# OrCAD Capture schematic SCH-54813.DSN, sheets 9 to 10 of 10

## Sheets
9 05 SPI/I2C/ATX/CT: size C
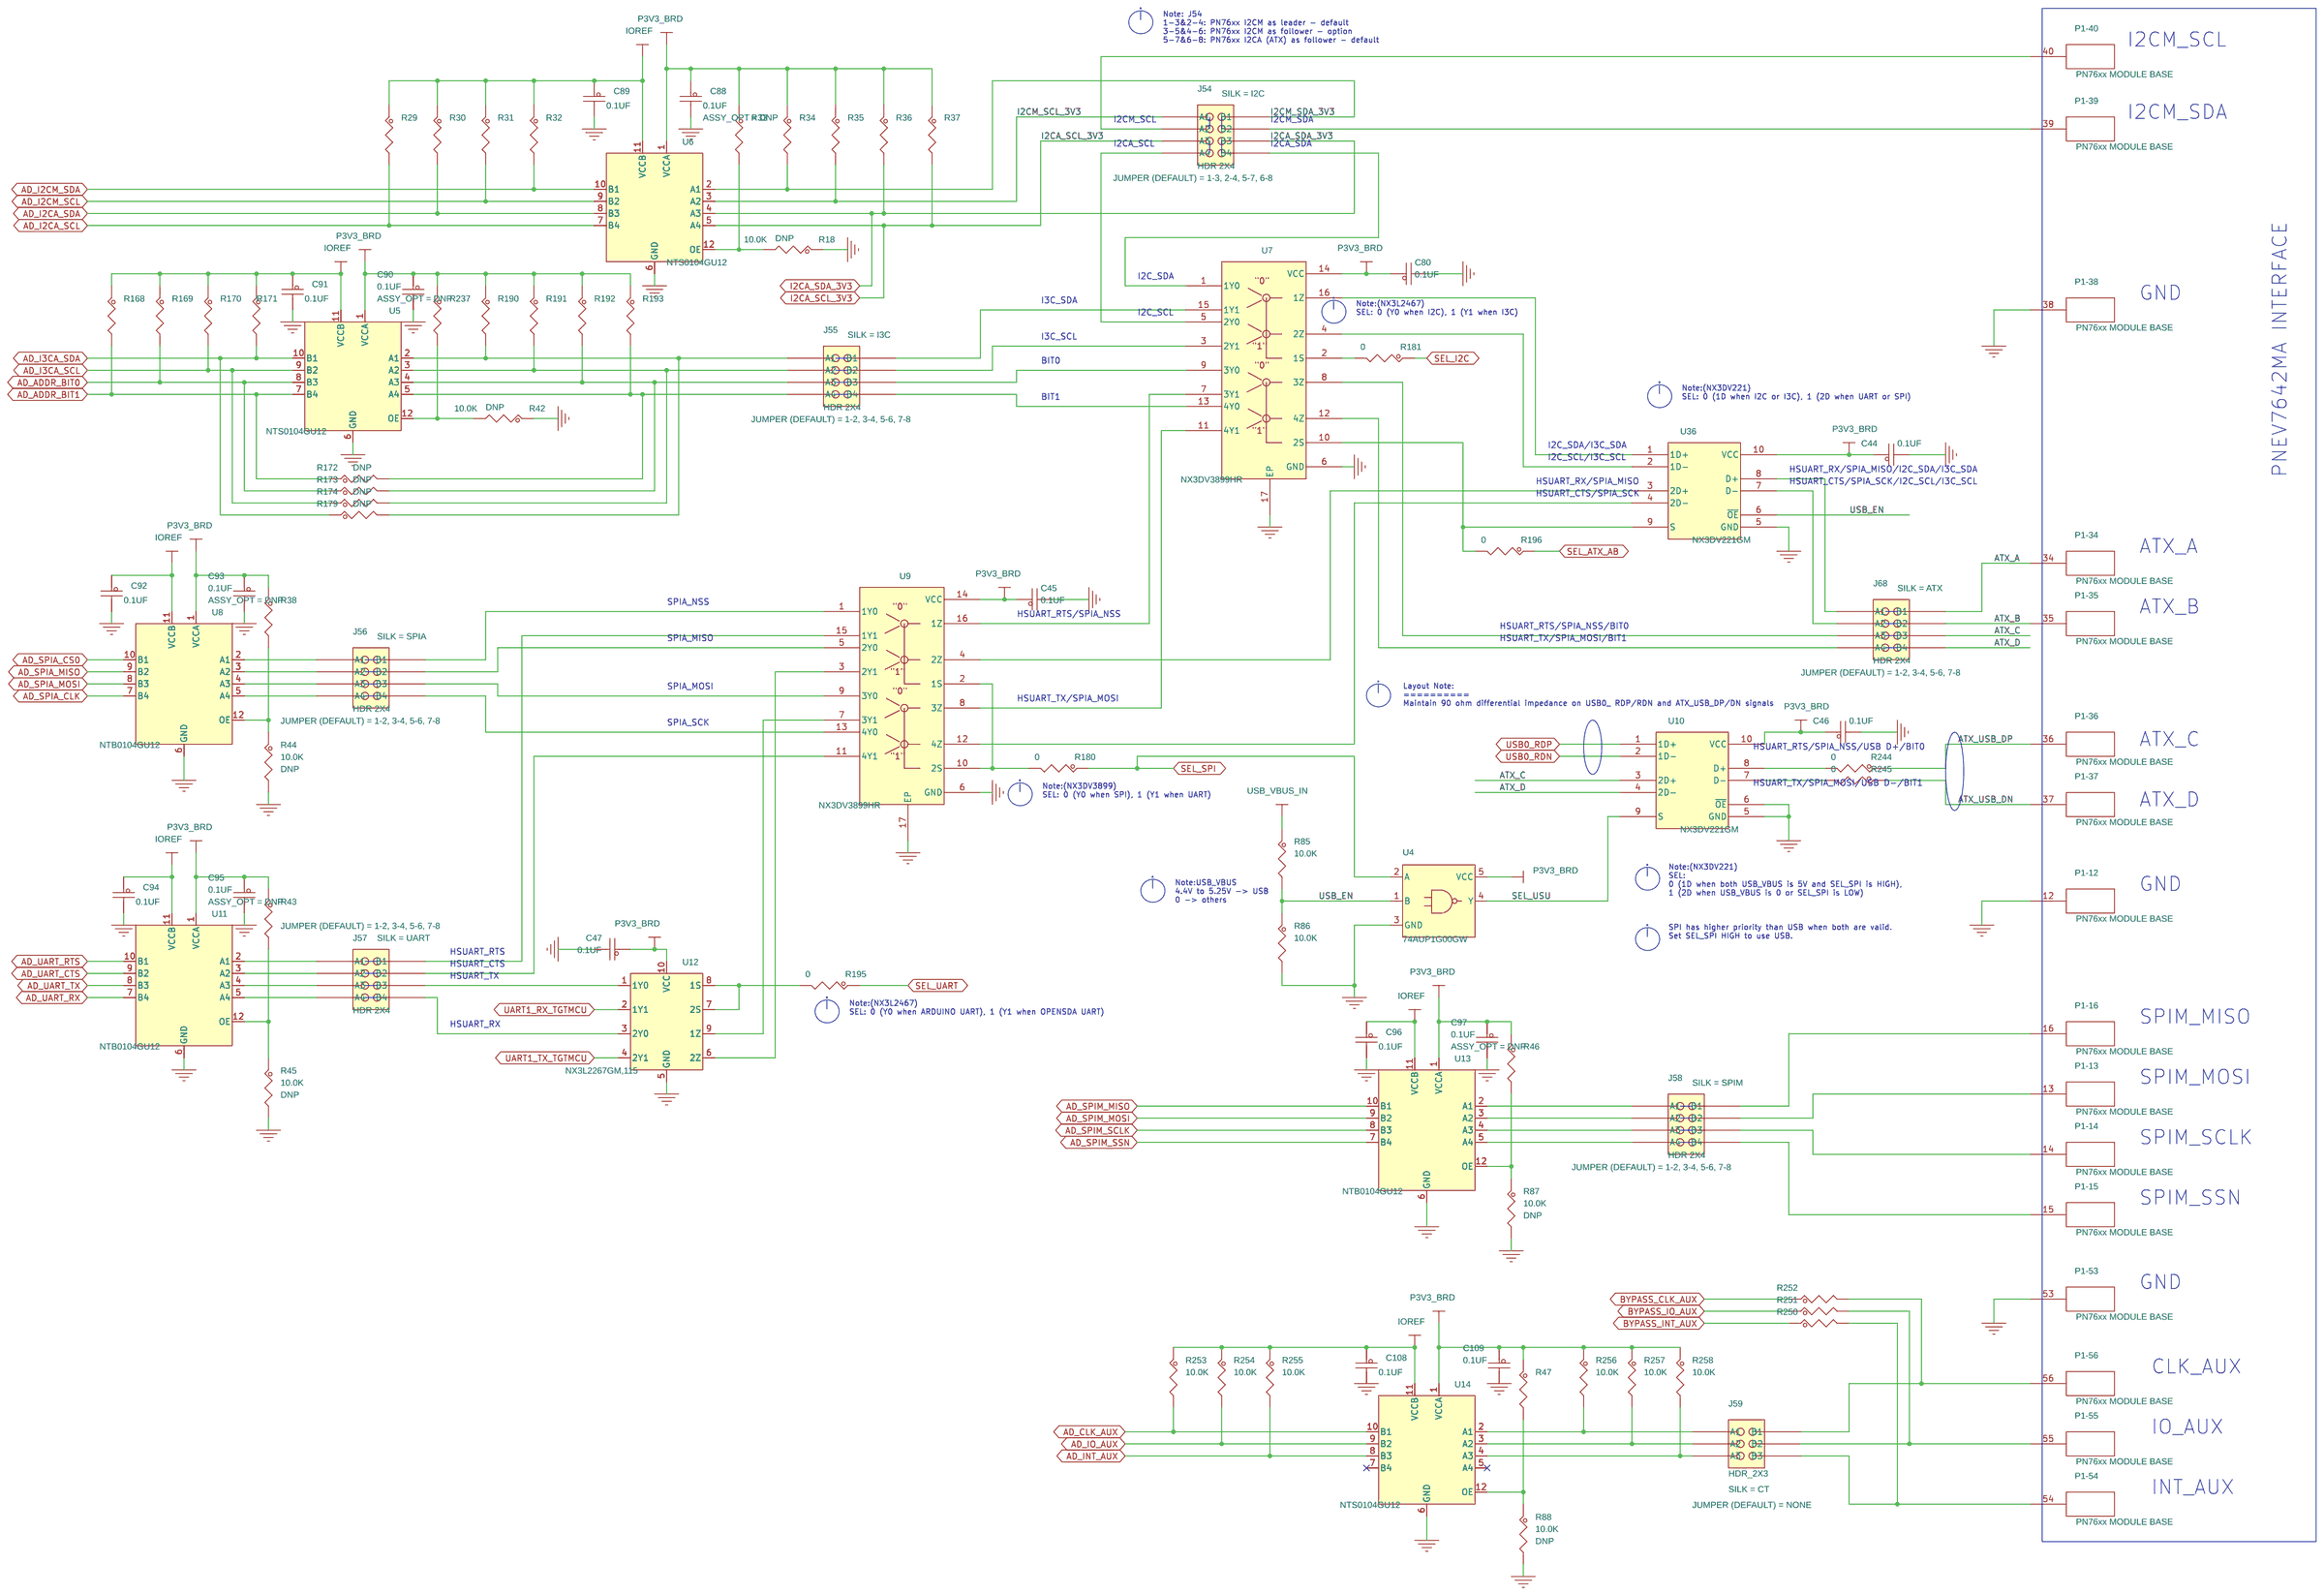
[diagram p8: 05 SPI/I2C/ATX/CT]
10 07 ANALOG/CONTROL: size C
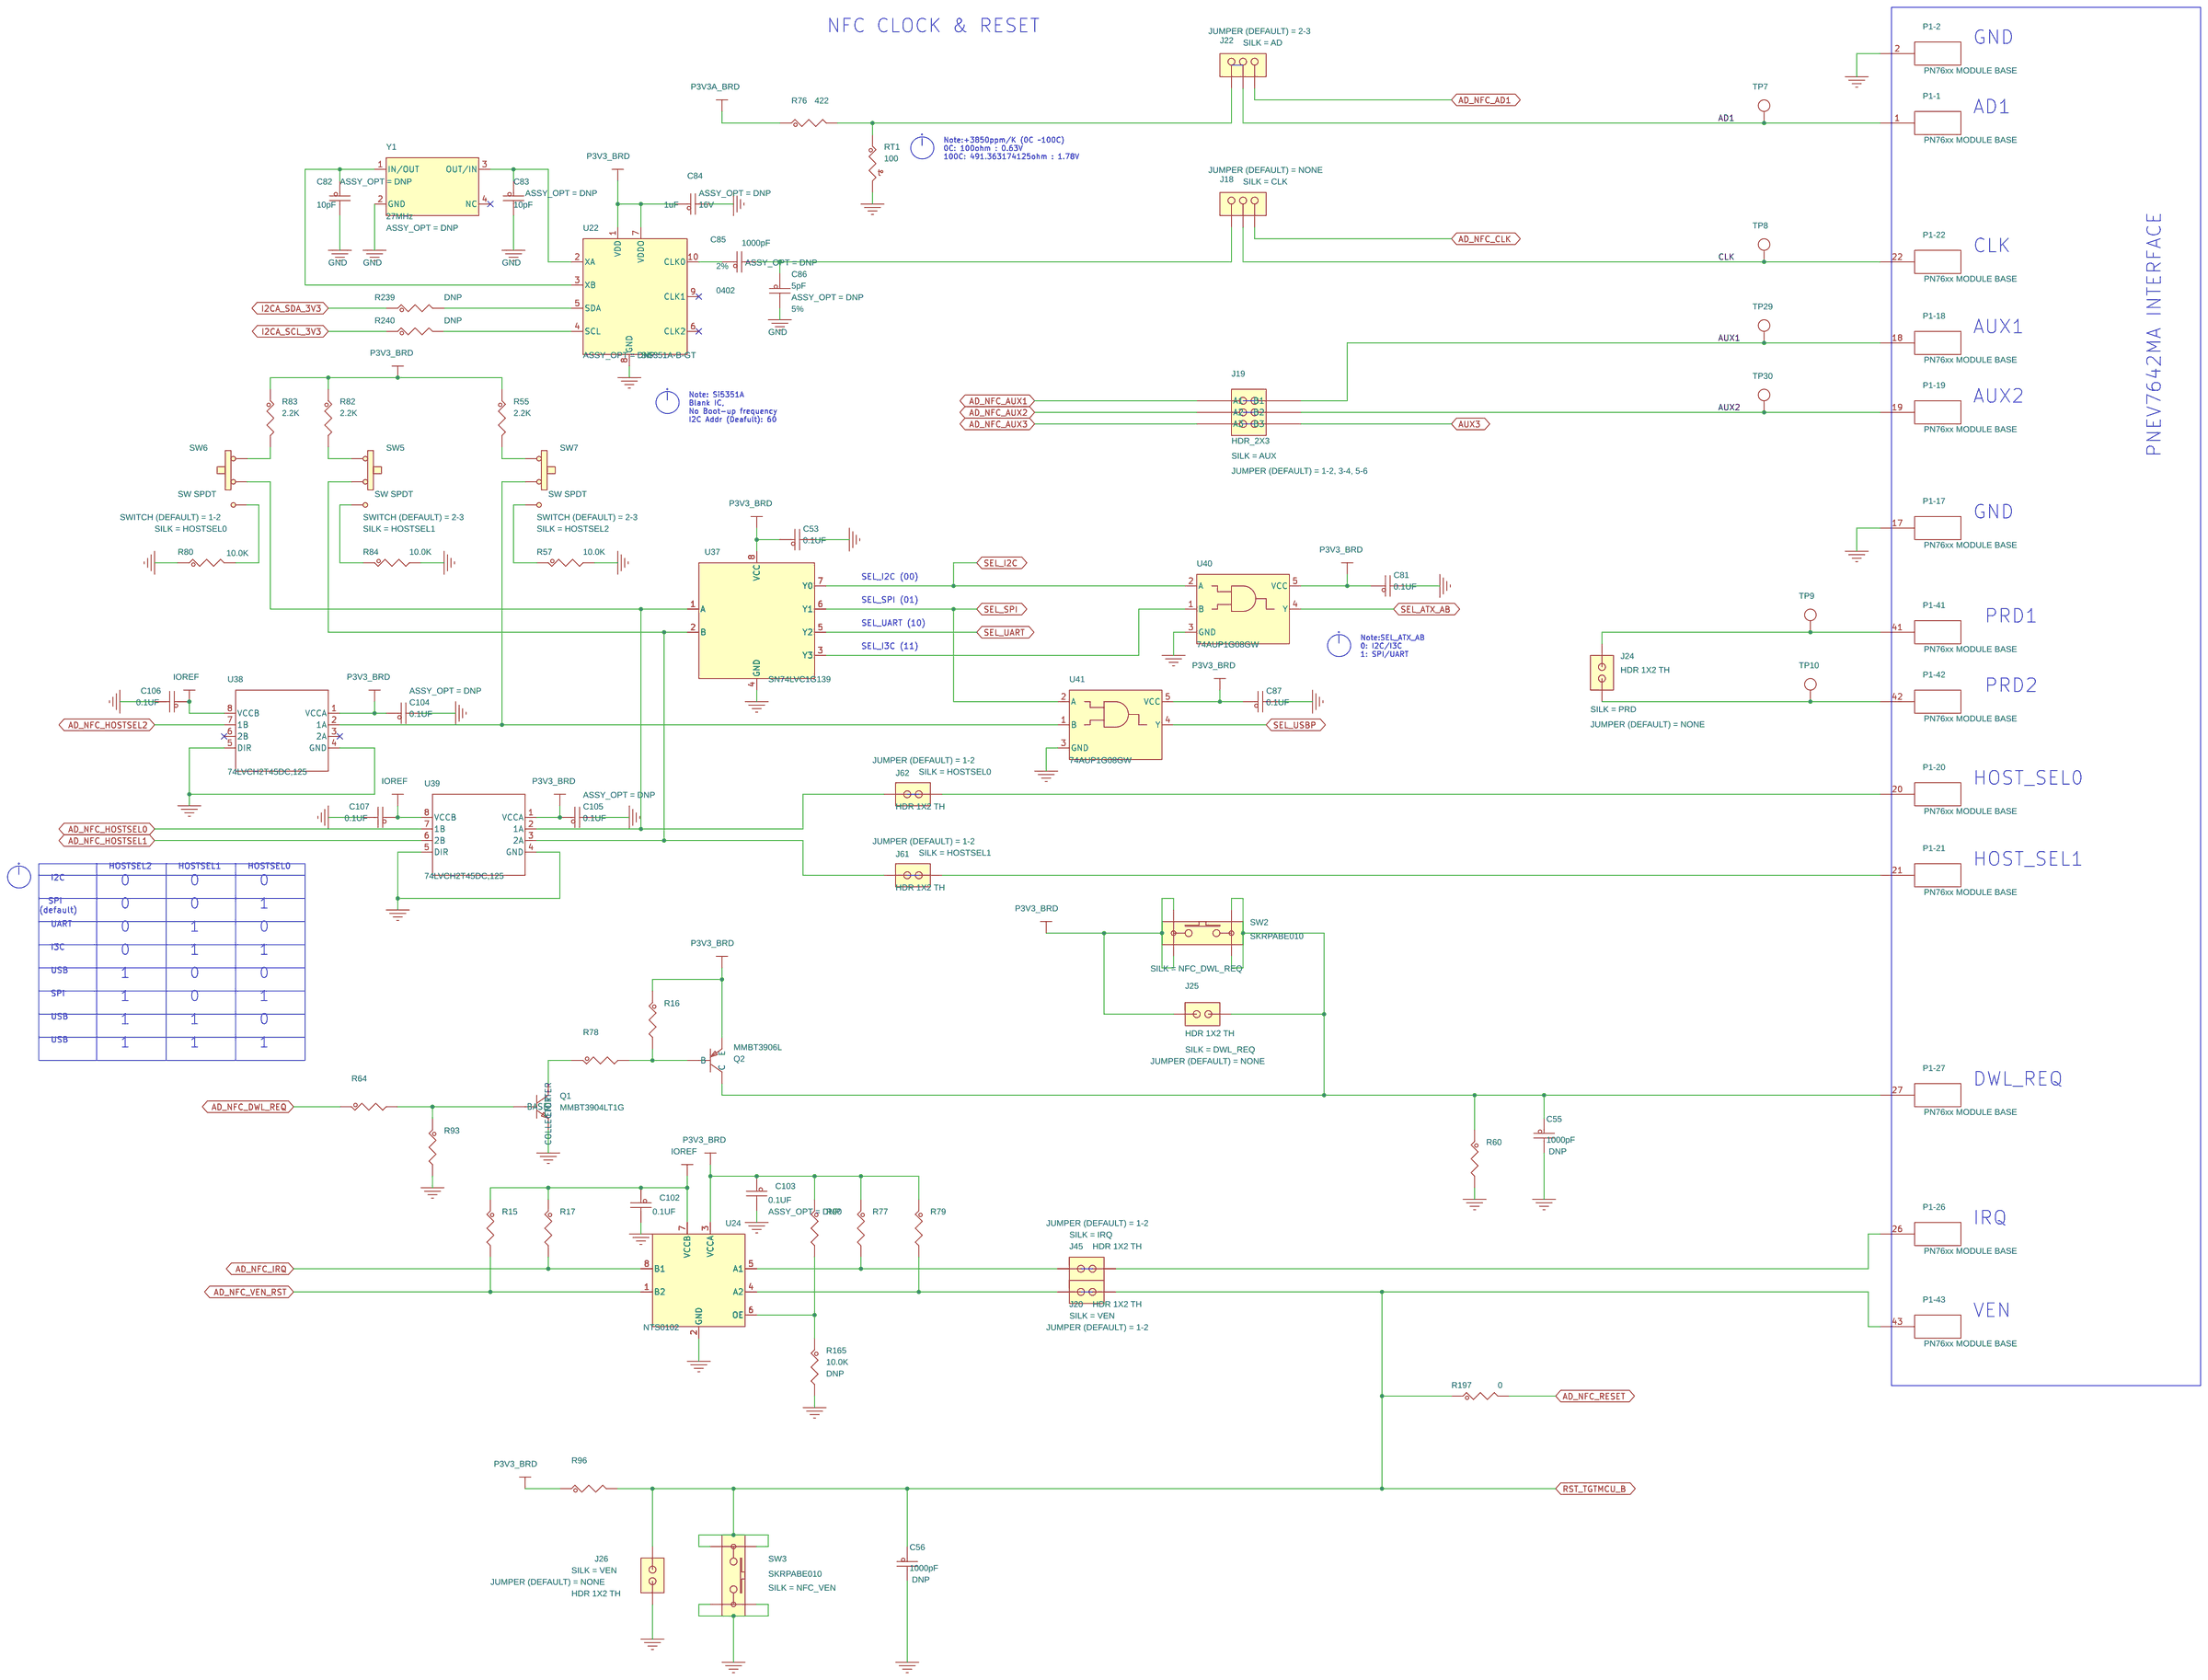
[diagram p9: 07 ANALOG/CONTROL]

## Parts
sheet 05 SPI/I2C/ATX/CT
C44  0.1UF  [CC0402_25]
C45  0.1UF  [CC0402_25]
C46  0.1UF  [CC0402_25]
C47  0.1UF  [CC0402_25]
C80  0.1UF  [CC0402_25]
C88  0.1UF  [CC0402_25]
C89  0.1UF  [CC0402_25]
C90  0.1UF  [CC0402_25]
C91  0.1UF  [CC0402_25]
C92  0.1UF  [CC0402_25]
C93  0.1UF  [CC0402_25]
C94  0.1UF  [CC0402_25]
C95  0.1UF  [CC0402_25]
C96  0.1UF  [CC0402_25]
C97  0.1UF  [CC0402_25]
C108  0.1UF  [CC0402_25]
C109  0.1UF  [CC0402_25]
J54  HDR 2X4  [HDR2X4]
J55  HDR 2X4  [HDR2X4]
J56  HDR 2X4  [HDR2X4]
J57  HDR 2X4  [HDR2X4]
J58  HDR 2X4  [HDR2X4]
J59  HDR_2X3  [HDR203]
J68  HDR 2X4  [HDR2X4]
R18  10.0K  [RC0402_25]
R29  4.7K  [RC0402_25]
R30  4.7K  [RC0402_25]
R31  4.7K  [RC0402_25]
R32  4.7K  [RC0402_25]
R33  4.7K  [RC0402_25]
R34  4.7K  [RC0402_25]
R35  4.7K  [RC0402_25]
R36  4.7K  [RC0402_25]
R37  4.7K  [RC0402_25]
R38  4.7K  [RC0402_25]
R42  10.0K  [RC0402_25]
R43  4.7K  [RC0402_25]
R44  10.0K  [RC0402_25]
R45  10.0K  [RC0402_25]
R46  4.7K  [RC0402_25]
R47  4.7K  [RC0402_25]
R85  10.0K  [RC0402_25]
R86  10.0K  [RC0402_25]
R87  10.0K  [RC0402_25]
R88  10.0K  [RC0402_25]
R168  4.7K  [RC0402_25]
R169  4.7K  [RC0402_25]
R170  4.7K  [RC0402_25]
R171  4.7K  [RC0402_25]
R172  0  [RC0603_OV]
R173  0  [RC0603_OV]
R174  0  [RC0603_OV]
R179  0  [RC0603_OV]
R180  0  [RC0603_OV]
R181  0  [RC0603_OV]
R190  4.7K  [RC0402_25]
R191  4.7K  [RC0402_25]
R192  4.7K  [RC0402_25]
R193  4.7K  [RC0402_25]
R195  0  [RC0603_OV]
R196  0  [RC0603_OV]
R237  4.7K  [RC0402_25]
R244  0  [RC0603_OV]
R245  0  [RC0603_OV]
R250  0  [RC0603_OV]
R251  0  [RC0603_OV]
R252  0  [RC0603_OV]
R253  10.0K  [RC0402_25]
R254  10.0K  [RC0402_25]
R255  10.0K  [RC0402_25]
R256  10.0K  [RC0402_25]
R257  10.0K  [RC0402_25]
R258  10.0K  [RC0402_25]
U4  74AUP1G00GW  [sc70-5]
U5  NTS0104GU12  [xqfn12_0p4_1p8x2p1]
U6  NTS0104GU12  [xqfn12_0p4_1p8x2p1]
U7  NX3DV3899HR  [QFN16_0P5_3X3_EP]
U8  NTB0104GU12  [xqfn12_0p4_1p8x2p1]
U9  NX3DV3899HR  [QFN16_0P5_3X3_EP]
U10  NX3DV221GM  [xqfn10_0p5_1p65x2p1]
U11  NTB0104GU12  [xqfn12_0p4_1p8x2p1]
U12  NX3L2267GM,115  [XQFN10_0P5_1P65X2P1]
U13  NTB0104GU12  [xqfn12_0p4_1p8x2p1]
U14  NTS0104GU12  [xqfn12_0p4_1p8x2p1]
U36  NX3DV221GM  [xqfn10_0p5_1p65x2p1]
sheet 06 GPIO/DEBUG
P1  PN76xx MODULE BASE  [module56_1p52_23x23mm]  (sections -1,-10,-11,-12,-13,-14,-15,-16,-17,-18,-19,-2,-20,-21,-22,-23,-24,-25,-26,-27,-28,-29,-3,-30,-31,-32,-33,-34,-35,-36,-37,-38,-39,-4,-40,-41,-42,-43,-44,-45,-46,-47,-48,-49,-5,-50,-51,-52,-53,-54,-55,-56,-57,-6,-7,-8,-9)
sheet 07 ANALOG/CONTROL
C53  0.1UF  [CC0402_25]
C55  1000pF  [CC0402_25]
C56  1000pF  [CC0402_25]
C81  0.1UF  [CC0402_25]
C82  10pF  [CC0402_25]
C83  10pF  [CC0402_25]
C84  1uF  [CC0603_OV]
C85  1000pF  [CC0402_25]
C86  5pF  [CC0402_25]
C87  0.1UF  [CC0402_25]
C102  0.1UF  [CC0402_25]
C103  0.1UF  [CC0402_25]
C104  0.1UF  [CC0402_25]
C105  0.1UF  [CC0402_25]
C106  0.1UF  [CC0402_25]
C107  0.1UF  [CC0402_25]
J18  HDR TH 1X3  [HDR103]
J19  HDR_2X3  [HDR203]
J20  HDR 1X2 TH  [HDR_1X2]
J22  HDR TH 1X3  [HDR103]
J24  HDR 1X2 TH  [HDR_1X2]
J25  HDR 1X2 TH  [HDR_1X2]
J26  HDR 1X2 TH  [HDR_1X2]
J45  HDR 1X2 TH  [HDR_1X2]
J61  HDR 1X2 TH  [HDR_1X2]
J62  HDR 1X2 TH  [HDR_1X2]
Q1  MMBT3904LT1G  [SOT23_A]
Q2  MMBT3906L  [SOT23]
R15  4.7K  [RC0402_25]
R16  10.0K  [RC0402_25]
R17  4.7K  [RC0402_25]
R55  2.2K  [RC0402_25]
R57  10.0K  [RC0402_25]
R60  10.0K  [RC0402_25]
R64  10.0K  [RC0402_25]
R76  422  [RC0603_OV]
R77  4.7K  [RC0402_25]
R78  10.0K  [RC0402_25]
R79  4.7K  [RC0402_25]
R80  10.0K  [RC0402_25]
R82  2.2K  [RC0402_25]
R83  2.2K  [RC0402_25]
R84  10.0K  [RC0402_25]
R90  4.7K  [RC0402_25]
R93  10.0K  [RC0402_25]
R96  10.0K  [RC0402_25]
R165  10.0K  [RC0402_25]
R197  0  [RC0603_OV]
R239  0  [RC0603_OV]
R240  0  [RC0603_OV]
RT1  100  [RC0603_OV]
SW2  SKRPABE010  [sw4_skrp]
SW3  SKRPABE010  [sw4_skrp]
SW5  SW SPDT  [SW3_SPDT_SLIDE]
SW6  SW SPDT  [SW3_SPDT_SLIDE]
SW7  SW SPDT  [SW3_SPDT_SLIDE]
TP7  TPAD_040  [TPAD_040]
TP8  TPAD_040  [TPAD_040]
TP9  TPAD_040  [TPAD_040]
TP10  TPAD_040  [TPAD_040]
TP29  TPAD_040  [TPAD_040]
TP30  TPAD_040  [TPAD_040]
U22  Si5351A-B-GT  [MSOP_10_0P5_3X3]
U24  NTS0102  [tssop8_a]
U37  SN74LVC1G139  [psop8]
U38  74LVCH2T45DC,125  [ssop8_dcu]
U39  74LVCH2T45DC,125  [ssop8_dcu]
U40  74AUP1G08GW  [sc70-5]
U41  74AUP1G08GW  [sc70-5]
Y1  27MHz  [xtal4_1p6x1p2]

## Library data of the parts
C44-C47 C53 C80 C81 C87 C89 C91 C92 C94 C96 C102 C106-C109 = CAP_NP: CAP CER 0.1UF 50V 10% X5R 0402; AGILE_PN: 150-79249; CAD_APPROVED: Yes; FPLIST: CC0402_25,CC0402_HD,0402_CC,capc0402_l; HEIGHT: 0.55MM; MFG_NAME01: MURATA; MFG_PN01: GRM155R61H104KE19; ROHS: Yes; Rated Voltage: 50V; TOL: 10%; Temp Range: -55C to +85C; Tolerance: 10%; VOLTAGE: 50V
C88 C90 C93 C95 C97 C103-C105 = CAP_NP: CAP CER 0.1UF 50V 10% X5R 0402; AGILE_PN: 150-79249; ASSY_OPT: DNP; CAD_APPROVED: Yes; FPLIST: CC0402_25,CC0402_HD,0402_CC,capc0402_l; HEIGHT: 0.55MM; MFG_NAME01: MURATA; MFG_PN01: GRM155R61H104KE19; ROHS: Yes; Rated Voltage: 50V; TOL: 10%; Temp Range: -55C to +85C; Tolerance: 10%; VOLTAGE: 50V
J54 = CONN_HDR_4X2: HDR 2X4 TH 100MIL CTR 338H AU 100L; 3D_Mechanical_Footprint_File: http://fcl.am.freescale.net/ALLEGRO/step/hdr2x4_100l.STEP; AGILE_PN: 210-81059; CAD_APPROVED: Yes; HEIGHT: 8.59MM; JUMPER (DEFAULT): 1-3, 2-4, 5-7, 6-8; MFG_NAME01: SAMTEC; MFG_PN01: TSW-104-07-F-D; ROHS: Yes; SILK: I2C; Temp Range: -55°C to +125°C
J55 = CONN_HDR_4X2: HDR 2X4 TH 100MIL CTR 338H AU 100L; 3D_Mechanical_Footprint_File: http://fcl.am.freescale.net/ALLEGRO/step/hdr2x4_100l.STEP; AGILE_PN: 210-81059; CAD_APPROVED: Yes; HEIGHT: 8.59MM; JUMPER (DEFAULT): 1-2, 3-4, 5-6, 7-8; MFG_NAME01: SAMTEC; MFG_PN01: TSW-104-07-F-D; ROHS: Yes; SILK: I3C; Temp Range: -55°C to +125°C
J56 = CONN_HDR_4X2: HDR 2X4 TH 100MIL CTR 338H AU 100L; 3D_Mechanical_Footprint_File: http://fcl.am.freescale.net/ALLEGRO/step/hdr2x4_100l.STEP; AGILE_PN: 210-81059; CAD_APPROVED: Yes; HEIGHT: 8.59MM; JUMPER (DEFAULT): 1-2, 3-4, 5-6, 7-8; MFG_NAME01: SAMTEC; MFG_PN01: TSW-104-07-F-D; ROHS: Yes; SILK: SPIA; Temp Range: -55°C to +125°C
J57 = CONN_HDR_4X2: HDR 2X4 TH 100MIL CTR 338H AU 100L; 3D_Mechanical_Footprint_File: http://fcl.am.freescale.net/ALLEGRO/step/hdr2x4_100l.STEP; AGILE_PN: 210-81059; CAD_APPROVED: Yes; HEIGHT: 8.59MM; JUMPER (DEFAULT): 1-2, 3-4, 5-6, 7-8; MFG_NAME01: SAMTEC; MFG_PN01: TSW-104-07-F-D; ROHS: Yes; SILK: UART; Temp Range: -55°C to +125°C
J58 = CONN_HDR_4X2: HDR 2X4 TH 100MIL CTR 338H AU 100L; 3D_Mechanical_Footprint_File: http://fcl.am.freescale.net/ALLEGRO/step/hdr2x4_100l.STEP; AGILE_PN: 210-81059; CAD_APPROVED: Yes; HEIGHT: 8.59MM; JUMPER (DEFAULT): 1-2, 3-4, 5-6, 7-8; MFG_NAME01: SAMTEC; MFG_PN01: TSW-104-07-F-D; ROHS: Yes; SILK: SPIM; Temp Range: -55°C to +125°C
J59 = CONN_HDR_3X2: HDR 2X3 TH 100MIL CTR 338H AU 100L; 3D_Mechanical_Footprint_File: http://fcl.am.freescale.net/ALLEGRO/step/hdr203.STEP; AGILE_PN: 210-81057; CAD_APPROVED: Yes; HEIGHT: 8.59MM; JUMPER (DEFAULT): NONE; MFG_NAME01: SAMTEC; MFG_PN01: TSW-103-07-F-D; ROHS: Yes; SILK: CT; Temp Range: -55°C to +125°C
J68 = CONN_HDR_4X2: HDR 2X4 TH 100MIL CTR 338H AU 100L; 3D_Mechanical_Footprint_File: http://fcl.am.freescale.net/ALLEGRO/step/hdr2x4_100l.STEP; AGILE_PN: 210-81059; CAD_APPROVED: Yes; HEIGHT: 8.59MM; JUMPER (DEFAULT): 1-2, 3-4, 5-6, 7-8; MFG_NAME01: SAMTEC; MFG_PN01: TSW-104-07-F-D; ROHS: Yes; SILK: ATX; Temp Range: -55°C to +125°C
R18 R42 R44 R45 R87 R88 R165 = RES: RES MF 10.0K 1/16W 1% AEC-Q200 0402; AGILE_PN: 470-75416; ASSY_OPT: DNP; CAD_APPROVED: Yes; FPLIST: RC0402_25,RC0402_HD,0402_CC; HEIGHT: 0.4MM; MFG_NAME01: KOA SPEER; MFG_PN01: RK73H1ETTP1002F; ROHS: Yes; SIGNAL_MODEL: DEFAULT_RESISTOR_10000OHM_2_1; TOL: 5%; Temp Range: –55 °C to +155 °C; Tolerance: 1%
R15 R17 R29-R38 R43 R46 R47 R77 R79 R90 R168-R171 R190-R193 R237 = RES: RES MF 4.70K 1/16W 1% 0402; AGILE_PN: 470-75418; CAD_APPROVED: Yes; FPLIST: RC0402_25,RC0402_HD,0402_CC; HEIGHT: 0.4mm; MFG_NAME01: WALSIN TECHNOLOGY CORP.; MFG_PN01: WR04X4701FTL; ROHS: Yes; TOL: 1%; Tolerance: 1%; VOLTAGE: 1/16W
R57 R80 R84-R86 R253-R258 = RES: RES MF 10.0K 1/16W 1% AEC-Q200 0402; AGILE_PN: 470-75416; CAD_APPROVED: Yes; FPLIST: RC0402_25,RC0402_HD,0402_CC; HEIGHT: 0.4MM; MFG_NAME01: KOA SPEER; MFG_PN01: RK73H1ETTP1002F; ROHS: Yes; SIGNAL_MODEL: DEFAULT_RESISTOR_10000OHM_2_1; TOL: 5%; Temp Range: –55 °C to +155 °C; Tolerance: 1%
R172-R174 R179 R239 R240 = RES: RES MF ZERO OHM 1/10W -- 0603; AGILE_PN: 470-80866; ASSY_OPT: DNP; CAD_APPROVED: Yes; FPLIST: RC0603_OV,RC0603,R603-X2,0603_CC,IND_0603HP_NSP,CC0603_OV_NSP; HEIGHT: 0.6MM; MFG_NAME01: YAGEO AMERICA; MFG_PN01: RC0603FR-070RL; ROHS: Yes; TOL: 5%; Temp Range: –55 °C to +155 °C
R180 R181 R195-R197 R244 R245 = RES: RES MF ZERO OHM 1/10W -- 0603; AGILE_PN: 470-80866; CAD_APPROVED: Yes; FPLIST: RC0603_OV,RC0603,R603-X2,0603_CC; HEIGHT: 0.6MM; MFG_NAME01: YAGEO AMERICA; MFG_PN01: RC0603FR-070RL; ROHS: Yes; TOL: 1%; Temp Range: –55 °C to +155 °C
R250-R252 = RES: RES MF ZERO OHM 1/10W -- 0603; AGILE_PN: 470-80866; CAD_APPROVED: Yes; FPLIST: RC0603_OV,RC0603,R603-X2,0603_CC,IND_0603HP_NSP,CC0603_OV_NSP; HEIGHT: 0.6MM; MFG_NAME01: YAGEO AMERICA; MFG_PN01: RC0603FR-070RL; ROHS: Yes; TOL: 5%; Temp Range: –55 °C to +155 °C
U4 = 74AUP1G00GW: IC GATE NAND 2IN 0.8-3.6V.TSSOP5; 3D_Mechanical_Footprint_File: http://fcl.am.freescale.net/ALLEGRO/step/sc70-5.STEP; AGILE_PN: 312-81222; CAD_APPROVED: Yes; HEIGHT: 1.1MM; MFG_NAME01: NEXPERIA; MFG_PN01: 74AUP1G00GW,125; ROHS: Yes; VOLTAGE: 0.8-3.6V.
U5 U6 U14 = NTS0104GU12_12P: IC DUAL VXLTR XCVR 4BIT 1.65-3.6/2.3-5.5V XQFN12; 3D_Mechanical_Footprint_File: http://fcl.am.freescale.net/ALLEGRO/step/xqfn12_0p4_1p8x2p1.step; AGILE_PN: 312-82046; CAD_APPROVED: Yes; HEIGHT: 0.5MM; MFG_NAME01: NXP SEMICONDUCTORS; ROHS: Yes; Temp Range: -40 to +125C; VOLTAGE: 1.65-3.6/2.3-5.5V
U7 U9 = NX3DV3899HR: IC LIN SW DPDT 1.4-4.3V QFN16; 3D_Mechanical_Footprint_File: http://fcl.am.freescale.net/ALLEGRO/step/qfn16_0p5_3x3_ep.STEP; AGILE_PN: 315-80655; CAD_APPROVED: Yes; HEIGHT: 0.5MM; MFG_NAME01: NXP SEMICONDUCTORS; MFG_PN01: NX3DV3899HRZ; ROHS: Yes; VOLTAGE: 1.4-4.3V
U8 U11 U13 = NTB0104GU12_12P: IC DUAL VXLTR XCVR 4BIT 1.2-3.6/1.65-5.5V XQFN12; 3D_Mechanical_Footprint_File: http://fcl.am.freescale.net/ALLEGRO/step/xqfn12_0p4_1p8x2p1.step; AGILE_PN: 312-81869; CAD_APPROVED: Yes; HEIGHT: 0.5MM; MFG_NAME01: NXP SEMICONDUCTORS; ROHS: Yes; Temp Range: -40C to +125C; VOLTAGE: 1.2-3.6/1.65-5.5V
U10 U36 = NX3DV221GM_QFN_10P: IC USB 2.0 SWITCH HS 2.3-3.6V XQFN10; 3D_Mechanical_Footprint_File: http://fcl.am.freescale.net/ALLEGRO/step/xqfn10_0p5_1p65x2p1.step; AGILE_PN: 315-80882; CAD_APPROVED: Yes; HEIGHT: 0.5MM; MFG_NAME01: NXP SEMICONDUCTORS; MFG_PN01: NX3DV221GM,115; ROHS: Yes; VOLTAGE: 2.3-3.6V
U12 = NX3L2267GM_QFN10: IC ANALOG SW DUAL SPDT 1.4-4.3V XQFN10; 3D_Mechanical_Footprint_File: http://fcl.am.freescale.net/ALLEGRO/step/xqfn10_0p5_1p65x2p1.step; AGILE_PN: 315-81532; CAD_APPROVED: Yes; HEIGHT: 0.5 MM; MFG_NAME01: NXP SEMICONDUCTORS; ROHS: Yes; Temp Range: -40°C to +125°C; VOLTAGE: 1.4-4.3V
P1 = TP_RECT_56P_EP: NFC MODULE 4X14 23X23MM NO PART TO ORDER; AGILE_PN: 510-78458; CAD_APPROVED: Yes; HEIGHT: 2.35 MM; ROHS: Yes
C55 C56 = CAP_NP: CAP CER 1000pF 50V 10% X7R AEC-Q200 0402; AGILE_PN: 150-79040; ASSY_OPT: DNP; CAD_APPROVED: Yes; FPLIST: CC0402_25,CC0402_HD,0402_CC; HEIGHT: 0.55MM; MFG_NAME01: MURATA; MFG_PN01: GCM155R71H102KA37D; Package Size: 0402; Package Type: Paper Tape; ROHS: Yes; Rated Voltage: 50V; Temp Range: -55C to +125C; Tolerance: 10%; VOLTAGE: 50V
C82 C83 = CAP_NP: CAP CER 10pF 50V 2% C0G 0402; AGILE_PN: 150-78893; ASSY_OPT: DNP; CAD_APPROVED: Yes; FPLIST: CC0402_25,CC0402_HD,0402_CC; HEIGHT: 0.55 MM; MFG_NAME01: MURATA; MFG_PN01: GJM1555C1H100GB01D; Package Size: 0402; Package Type: 180mm Paper Tape; ROHS: Yes; Rated Voltage: 50V; SIZE: 0402; Temp Range: -55C to +125C; Temp_Range: -55°C to +125°C; Tolerance: 2%; VOLTAGE: 50V
C84 = CAP_NP: CAP CER 1uF 16V 10% X7R 0603; AGILE_PN: 150-79460; ASSY_OPT: DNP; CAD_APPROVED: Yes; FPLIST: CC0603_OV,CC0603,0603_CC; HEIGHT: 0.9 MM; MFG_NAME01: TDK; MFG_PN01: C1608X7R1C105K080AC; Package Size: 0603; ROHS: Yes; Rated Voltage: 16V; Temp Range: -55C to +125C; Tolerance: 10%; VOLTAGE: 16V
C85 = CAP_NP: CAP CER 1000pF 50V 2% C0G 0402; AGILE_PN: 150-79726; ASSY_OPT: DNP; CAD_APPROVED: Yes; FPLIST: CC0402_25,CC0402_HD,0402_CC; HEIGHT: 0.55MM; MFG_NAME01: MURATA; MFG_PN01: GRM1555C1H102GA01D; Package Size: 0402; Package Type: SMD; ROHS: Yes; Rated Voltage: 50V; SIZE: 0402; Temp Range: -55C to +125C; Temp_Range: -55°C to +125°C; Tolerance: 2%; VOLTAGE: 50V
C86 = CAP_NP: CAP CER 5PF 16V 5% C0G CC0402; AGILE_PN: 150-75578; ASSY_OPT: DNP; CAD_APPROVED: Yes; FPLIST: CC0402_25,CC0402_HD,0402_CC; HEIGHT: 0.55 MM; MFG_NAME01: SMEC; MFG_PN01: MCCA050J0NOTF; ROHS: Yes; Rated Voltage: 16V; Temp Range: -55C to +125C; Temp_Range: -55°C to +125°C; Tolerance: 5%; VOLTAGE: 16V
J18 = CONN_HDR_3X1: HDR 1X3 TH 100MIL SP 339H AU 100L; 3D_Mechanical_Footprint_File: http://fcl.am.freescale.net/ALLEGRO/step/hdr103.STEP; AGILE_PN: 210-75726; CAD_APPROVED: Yes; HEIGHT: 8.65MM; JUMPER (DEFAULT): NONE; MFG_NAME01: SAMTEC; MFG_PN01: TSW-103-07-G-S; Package Size: 7.62 x 2.54 mm; ROHS: Yes; SILK: CLK; Temp Range: -55°C to +125°C; VOLTAGE: 450 - 550 VAC
J19 = CONN_HDR_3X2: HDR 2X3 TH 100MIL CTR 338H AU 100L; 3D_Mechanical_Footprint_File: http://fcl.am.freescale.net/ALLEGRO/step/hdr203.STEP; AGILE_PN: 210-81057; CAD_APPROVED: Yes; HEIGHT: 8.59MM; JUMPER (DEFAULT): 1-2, 3-4, 5-6; MFG_NAME01: SAMTEC; MFG_PN01: TSW-103-07-F-D; ROHS: Yes; SILK: AUX; Temp Range: -55°C to +125°C
J20 = HDR_1X2_TH: HDR 1X2 TH 100MIL SP 339H AU 98L; 3D_Mechanical_Footprint_File: http://fcl.am.freescale.net/ALLEGRO/step/hdr102_338h.STEP; AGILE_PN: 210-75439; CAD_APPROVED: YES; FPLIST: HDR102,SH_HDR102_BOTTOM; HEIGHT: 8.71 MM; JUMPER (DEFAULT): 1-2; MFG_NAME01: SAMTEC; MFG_PN01: TSW-102-07-G-S; ROHS: Yes; SILK: VEN; Temp Range: -55°C to +125°C
J22 = CONN_HDR_3X1: HDR 1X3 TH 100MIL SP 339H AU 100L; 3D_Mechanical_Footprint_File: http://fcl.am.freescale.net/ALLEGRO/step/hdr103.STEP; AGILE_PN: 210-75726; CAD_APPROVED: Yes; HEIGHT: 8.65MM; JUMPER (DEFAULT): 2-3; MFG_NAME01: SAMTEC; MFG_PN01: TSW-103-07-G-S; Package Size: 7.62 x 2.54 mm; ROHS: Yes; SILK: AD; Temp Range: -55°C to +125°C; VOLTAGE: 450 - 550 VAC
J24 = HDR_1X2_TH: HDR 1X2 TH 100MIL SP 339H AU 98L; 3D_Mechanical_Footprint_File: http://fcl.am.freescale.net/ALLEGRO/step/hdr102_338h.STEP; AGILE_PN: 210-75439; CAD_APPROVED: YES; FPLIST: HDR102,SH_HDR102_BOTTOM; HEIGHT: 8.71 MM; JUMPER (DEFAULT): NONE; MFG_NAME01: SAMTEC; MFG_PN01: TSW-102-07-G-S; ROHS: Yes; SILK: PRD; Temp Range: -55°C to +125°C
J25 = HDR_1X2_TH: HDR 1X2 TH 100MIL SP 339H AU 98L; 3D_Mechanical_Footprint_File: http://fcl.am.freescale.net/ALLEGRO/step/hdr102_338h.STEP; AGILE_PN: 210-75439; CAD_APPROVED: YES; FPLIST: HDR102,SH_HDR102_BOTTOM; HEIGHT: 8.71 MM; JUMPER (DEFAULT): NONE; MFG_NAME01: SAMTEC; MFG_PN01: TSW-102-07-G-S; ROHS: Yes; SILK: DWL_REQ; Temp Range: -55°C to +125°C
J26 = HDR_1X2_TH: HDR 1X2 TH 100MIL SP 339H AU 98L; 3D_Mechanical_Footprint_File: http://fcl.am.freescale.net/ALLEGRO/step/hdr102_338h.STEP; AGILE_PN: 210-75439; CAD_APPROVED: YES; FPLIST: HDR102,SH_HDR102_BOTTOM; HEIGHT: 8.71 MM; JUMPER (DEFAULT): NONE; MFG_NAME01: SAMTEC; MFG_PN01: TSW-102-07-G-S; ROHS: Yes; SILK: VEN; Temp Range: -55°C to +125°C
J45 = HDR_1X2_TH: HDR 1X2 TH 100MIL SP 339H AU 98L; 3D_Mechanical_Footprint_File: http://fcl.am.freescale.net/ALLEGRO/step/hdr102_338h.STEP; AGILE_PN: 210-75439; CAD_APPROVED: YES; FPLIST: HDR102,SH_HDR102_BOTTOM; HEIGHT: 8.71 MM; JUMPER (DEFAULT): 1-2; MFG_NAME01: SAMTEC; MFG_PN01: TSW-102-07-G-S; ROHS: Yes; SILK: IRQ; Temp Range: -55°C to +125°C
J61 = HDR_1X2_TH: HDR 1X2 TH 100MIL SP 339H AU 98L; 3D_Mechanical_Footprint_File: http://fcl.am.freescale.net/ALLEGRO/step/hdr102_338h.STEP; AGILE_PN: 210-75439; CAD_APPROVED: YES; FPLIST: HDR102,SH_HDR102_BOTTOM; HEIGHT: 8.71 MM; JUMPER (DEFAULT): 1-2; MFG_NAME01: SAMTEC; MFG_PN01: TSW-102-07-G-S; ROHS: Yes; SILK: HOSTSEL1; Temp Range: -55°C to +125°C
J62 = HDR_1X2_TH: HDR 1X2 TH 100MIL SP 339H AU 98L; 3D_Mechanical_Footprint_File: http://fcl.am.freescale.net/ALLEGRO/step/hdr102_338h.STEP; AGILE_PN: 210-75439; CAD_APPROVED: YES; FPLIST: HDR102,SH_HDR102_BOTTOM; HEIGHT: 8.71 MM; JUMPER (DEFAULT): 1-2; MFG_NAME01: SAMTEC; MFG_PN01: TSW-102-07-G-S; ROHS: Yes; SILK: HOSTSEL0; Temp Range: -55°C to +125°C
Q1 = NPN: TRAN NPN GEN 200MA 40V SOT-23; AGILE_PN: 480-75173; CAD_APPROVED: Yes; HEIGHT: 1.12 MM; MFG_NAME01: NEXPERIA; MFG_PN01: MMBT3904,215; ROHS: Yes
Q2 = PNP: TRAN PNP GEN 0.2A 40V SOT23; AGILE_PN: 480-75192; CAD_APPROVED: Yes; HEIGHT: 1.3MM; MFG_NAME01: ON SEMICONDUCTOR; MFG_PN01: MMBT3906LT1G; ROHS: Yes
R16 R60 R64 R78 R93 R96 = RES: RES MF 10.0K 1/16W 1% AEC-Q200 0402; AGILE_PN: 470-75416; CAD_APPROVED: Yes; FPLIST: RC0402_25,RC0402_HD,0402_CC; HEIGHT: 0.4MM; MFG_NAME01: KOA SPEER; MFG_PN01: RK73H1ETTP1002F; ROHS: Yes; TOL: 5%; Temp Range: –55 °C to +155 °C; Tolerance: 1%
R55 R82 R83 = RES: RES MF 2.2K 1/16W 5% 0402; AGILE_PN: 470-75636; CAD_APPROVED: Yes; FPLIST: RC0402_25,RC0402_HD,0402_CC; HEIGHT: 0.4 MM; MFG_NAME01: BOURNS; MFG_PN01: CR0402-JW-222GLF; ROHS: Yes; Tolerance: 5%
R76 = RES: RES MF 422 OHM 1/8W 1% AEC-Q200 0603; AGILE_PN: 470-81968; CAD_APPROVED: Yes; HEIGHT: 0.55MM; MFG_NAME01: KOA SPEER; MFG_PN01: RK73H1JTTD4220F; ROHS: Yes; Temp Range: -55C to +155C; Tolerance: 1%
RT1 = THERMISTOR: RES PLATINUM RTD SENSOR 100 OHM --0.3OHM AEC-Q200 0603; 3D_Mechanical_Footprint_File: http://fcl.am.freescale.net/ALLEGRO/step/PTS0603.STEP; AGILE_PN: 470-82747; CAD_APPROVED: Yes; HEIGHT: 0.55MM; MFG_NAME01: Vishay Beyschlag; MFG_PN01: PTS0603M1B100RP100; Package Size: 0603 (1608 Metric); Package Type: Surface Mount; ROHS: Yes; Temp Range: -55 °C to +175 °C
SW2 = SW_TC_SPST_4P: SW SPST PB SMT 16V 20MA; 3D_Mechanical_Footprint_File: http://fcl.am.freescale.net/ALLEGRO/step/sw4_skrp.step; AGILE_PN: 510-75638; CAD_APPROVED: Yes; HEIGHT: 2.5MM; MFG_NAME01: ALPS ELECTRIC (USA) INC.; ROHS: Yes; SILK: NFC_DWL_REQ; VOLTAGE: 16V
SW3 = SW_TC_SPST_4P: SW SPST PB SMT 16V 20MA; 3D_Mechanical_Footprint_File: http://fcl.am.freescale.net/ALLEGRO/step/sw4_skrp.step; AGILE_PN: 510-75638; CAD_APPROVED: Yes; HEIGHT: 2.5MM; MFG_NAME01: ALPS ELECTRIC (USA) INC.; ROHS: Yes; SILK: NFC_VEN; VOLTAGE: 16V
SW5 = SW3-SPDT-SLD: SW SPDT SLD 30V 0.1A TH; 3D_Mechanical_Footprint_File: http://fcl.am.freescale.net/ALLEGRO/step/sw3_spdt_slide.STEP; AGILE_PN: 510-75042; CAD_APPROVED: Yes; HEIGHT: 6.50MM; MFG_NAME01: NKK SWITCHES; MFG_PN01: SS12SDP2; ROHS: Yes; SILK: HOSTSEL1; SWITCH (DEFAULT): 2-3
SW6 = SW3-SPDT-SLD: SW SPDT SLD 30V 0.1A TH; 3D_Mechanical_Footprint_File: http://fcl.am.freescale.net/ALLEGRO/step/sw3_spdt_slide.STEP; AGILE_PN: 510-75042; CAD_APPROVED: Yes; HEIGHT: 6.50MM; MFG_NAME01: NKK SWITCHES; MFG_PN01: SS12SDP2; ROHS: Yes; SILK: HOSTSEL0; SWITCH (DEFAULT): 1-2
SW7 = SW3-SPDT-SLD: SW SPDT SLD 30V 0.1A TH; 3D_Mechanical_Footprint_File: http://fcl.am.freescale.net/ALLEGRO/step/sw3_spdt_slide.STEP; AGILE_PN: 510-75042; CAD_APPROVED: Yes; HEIGHT: 6.50MM; MFG_NAME01: NKK SWITCHES; MFG_PN01: SS12SDP2; ROHS: Yes; SILK: HOSTSEL2; SWITCH (DEFAULT): 2-3
TP7-TP10 TP29 TP30 = TESTLOOP: TEST POINT PAD 40MIL DIA SMT, NO PART TO ORDER; AGILE_PN: 211-76643; CAD_APPROVED: Yes; HEIGHT: 0.1MM; MFG_NAME01: NOTACOMPONENT; MFG_PN01: NOTACOMPONENT; ROHS: Yes
U22 = SI5351_MSOP_10P: IC CLK GEN 3-OUTPUT BLANK 2.5/3.3V MSOP10; AGILE_PN: 312-82173; ASSY_OPT: DNP; Aux Part Number: Si5351A-; CAD_APPROVED: Yes; HEIGHT: 1.1MM; MFG_NAME01: SILICON LABORATORIES; ROHS: Yes; ROOM: 09 ADC/ACMP Sources; Temp Range: -40°C to +85°C; Temp_Range: -40°C to +85°C; VOLTAGE: 2.25-3.6V
U24 = NTB0102_8P: IC XCVR 2-BIT 1.65-3.6V/2.3-5.5V TSSOP8; AGILE_PN: 312-80889; CAD_APPROVED: Yes; HEIGHT: 1.1MM; MFG_NAME01: NXP SEMICONDUCTORS; MFG_PN01: NTS0102DP; ROHS: Yes; VOLTAGE: 1.65-3.6V/2.3-5.5V
U37 = SN74LVC1G139_8P: IC DEMUX/DECODER 2 TO 4 1.65-5.5V VSSOP8; 3D_Mechanical_Footprint_File: http://fcl.am.freescale.net/ALLEGRO/step/psop8.STEP; AGILE_PN: 312-81722; CAD_APPROVED: Yes; HEIGHT: 0.9MM; MFG_NAME01: TEXAS INSTRUMENTS; MFG_PN01: SN74LVC1G139DCUT; ROHS: Yes; Temp Range: -40C to +85C; VOLTAGE: 1.65-5.5V
U38 U39 = 74LVC2T45DC_8P: IC VXLTR 2BIT BIDIR DUAL SUPPLY 1.2-5.5V VSSOP8; AGILE_PN: 312-82245; CAD_APPROVED: Yes; HEIGHT: 1MM; MFG_NAME01: NEXPERIA; ROHS: Yes; Temp Range: -40° C to +125° C; VOLTAGE: 1.2-5.5V
U40 U41 = 74AUP1G08: IC GATE AND 2IN 0.8-3.6V AEC-Q100 TSSOP5; 3D_Mechanical_Footprint_File: http://fcl.am.freescale.net/ALLEGRO/step/sc70-5.STEP; AGILE_PN: 312-81223; CAD_APPROVED: Yes; HEIGHT: 1.1MM; MFG_NAME01: NEXPERIA; MFG_PN01: 74AUP1G08GW,125; ROHS: Yes; VOLTAGE: 0.8-3.6V
Y1 = ECS-271.2-10-47Q-ES_4P: XTAL 27MHz 8pF 50ppm AEC-Q200 SMT; AGILE_PN: 230-78324; ASSY_OPT: DNP; CAD_APPROVED: Yes; HEIGHT: 0.4MM; MFG_NAME01: ECS INC. INTERNATIONAL; MFG_PN01: ECS-270-8-47Q-CES-TR; ROHS: Yes; Temp Range: -40°C to 125°C; Temp_Range: -40°C to 125°C

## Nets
GND: C44.2 C45.2 C46.2 C47.2 C53.2 C55.2 C56.2 C80.2 C81.2 C82.2 C83.2 C84.2 C86.2 C87.2 C88.2 C89.2 C90.2 C91.2 C92.2 C93.2 C94.2 C95.2 C96.2 C97.2 C102.2 C103.2 C104.2 C105.2 C106.2 C107.2 C108.2 C109.2 J26.2 P1.2 P1.12 P1.17 P1.38 P1.53 Q1.2(EMITTER) R18.1 R42.1 R44.2 R45.2 R57.2 R60.2 R80.1 R84.2 R86.2 R87.2 R88.2 R93.2 R165.2 RT1.2 SW3.1 SW3.2 U4.3(GND) U5.6(GND) U6.6(GND) U7.6(GND) U7.17(EP) U8.6(GND) U9.6(GND) U9.17(EP) U10.5(GND) U10.6(~{OE}) U11.6(GND) U12.5(GND) U13.6(GND) U14.6(GND) U22.8(GND) U24.2(GND) U36.5(GND) U37.4(GND) U38.4(GND) U38.5(DIR) U39.4(GND) U39.5(DIR) U40.3(GND) U41.3(GND) Y1.2(GND) ; also on sheet 3 4 5 6 7 8
P3V3_BRD: C44.1 C45.1 C46.1 C47.1 C53.1 C80.1 C81.1 C84.1 C87.1 C88.1 C90.1 C93.1 C95.1 C97.1 C103.1 C104.1 C105.1 C109.1 J25.1 Q2.2(E) R16.1 R33.1 R34.1 R35.1 R36.1 R37.1 R38.1 R43.1 R46.1 R47.1 R55.1 R77.1 R79.1 R82.1 R83.1 R90.1 R96.1 R190.1 R191.1 R192.1 R193.1 R237.1 R256.1 R257.1 R258.1 SW2.3 SW2.4 U4.5(VCC) U5.1(VCCA) U6.1(VCCA) U7.14(VCC) U8.1(VCCA) U9.14(VCC) U10.10(VCC) U11.1(VCCA) U12.10(VCC) U13.1(VCCA) U14.1(VCCA) U22.1(VDD) U22.7(VDDO) U24.3(VCCA) U36.10(VCC) U37.8(VCC) U38.1(VCCA) U39.1(VCCA) U40.5(VCC) U41.5(VCC) ; also on sheet 3 6 7 8
P3V3A_BRD: R76.1 ; also on sheet 3
AD1: J22.2 P1.1 TP7.1(Pin1)
AD_ADDR_BIT0: R169.2 R173.1 U5.8(B3) ; also on sheet 7
AD_ADDR_BIT1: R168.2 R172.1 U5.7(B4) ; also on sheet 7
AD_CLK_AUX: R253.2 U14.10(B1) ; also on sheet 7
AD_I2CA_SCL: R29.2 U6.7(B4) ; also on sheet 7
AD_I2CA_SDA: R30.2 U6.8(B3) ; also on sheet 7
AD_I2CM_SCL: R31.2 U6.9(B2) ; also on sheet 7
AD_I2CM_SDA: R32.2 U6.10(B1) ; also on sheet 7
AD_I3CA_SCL: R170.2 R174.1 U5.9(B2) ; also on sheet 7
AD_I3CA_SDA: R171.2 R179.1 U5.10(B1) ; also on sheet 7
AD_INT_AUX: R255.2 U14.8(B3) ; also on sheet 7
AD_IO_AUX: R254.2 U14.9(B2) ; also on sheet 7
AD_NFC_AD1: J22.1 ; also on sheet 7
AD_NFC_AUX1: J19.1(A1) ; also on sheet 7
AD_NFC_AUX2: J19.3(A2) ; also on sheet 7
AD_NFC_AUX3: J19.5(A3) ; also on sheet 7
AD_NFC_CLK: J18.1 ; also on sheet 7
AD_NFC_DWL_REQ: R64.1 ; also on sheet 7
AD_NFC_HOSTSEL0: U39.7(1B) ; also on sheet 7
AD_NFC_HOSTSEL1: U39.6(2B) ; also on sheet 7
AD_NFC_HOSTSEL2: U38.7(1B) ; also on sheet 7
AD_NFC_IRQ: R17.2 U24.8(B1) ; also on sheet 7
AD_NFC_RESET: R197.2 ; also on sheet 7
AD_NFC_VEN_RST: R15.2 U24.1(B2) ; also on sheet 7
AD_SPIA_CLK: U8.7(B4) ; also on sheet 7
AD_SPIA_CS0: U8.10(B1) ; also on sheet 7
AD_SPIA_MISO: U8.9(B2) ; also on sheet 7
AD_SPIA_MOSI: U8.8(B3) ; also on sheet 7
AD_SPIM_MISO: U13.10(B1) ; also on sheet 7
AD_SPIM_MOSI: U13.9(B2) ; also on sheet 7
AD_SPIM_SCLK: U13.8(B3) ; also on sheet 7
AD_SPIM_SSN: U13.7(B4) ; also on sheet 7
AD_UART_CTS: U11.9(B2) ; also on sheet 7
AD_UART_RTS: U11.10(B1) ; also on sheet 7
AD_UART_RX: U11.7(B4) ; also on sheet 7
AD_UART_TX: U11.8(B3) ; also on sheet 7
ATX_A: J68.2(B1) P1.34
ATX_B: J68.4(B2) P1.35
ATX_C: J68.6(B3) U10.3(2D+)
ATX_D: J68.8(B4) U10.4(2D-)
ATX_USB_DN: P1.37 R245.1
ATX_USB_DP: P1.36 R244.1
AUX1: J19.2(B1) P1.18 TP29.1(Pin1)
AUX2: J19.4(B2) P1.19 TP30.1(Pin1)
AUX3: J19.6(B3) ; also on sheet 4
BYPASS_CLK_AUX: R252.1 ; also on sheet 7
BYPASS_INT_AUX: R250.1 ; also on sheet 7
BYPASS_IO_AUX: R251.1 ; also on sheet 7
CLK: J18.2 P1.22 TP8.1(Pin1)
I2CA_SCL_3V3: J54.5(A3) R37.2 R240.1 U6.5(A4)
I2CA_SDA_3V3: J54.6(B3) R36.2 R239.1 U6.4(A3)
I2CM_SCL_3V3: J54.1(A1) R35.2 U6.3(A2)
I2CM_SDA_3V3: J54.2(B1) R34.2 U6.2(A1)
IOREF: C89.1 C91.1 C92.1 C94.1 C96.1 C102.1 C106.1 C107.1 C108.1 R15.1 R17.1 R29.1 R30.1 R31.1 R32.1 R168.1 R169.1 R170.1 R171.1 R253.1 R254.1 R255.1 U5.11(VCCB) U6.11(VCCB) U8.11(VCCB) U11.11(VCCB) U13.11(VCCB) U14.11(VCCB) U24.7(VCCB) U38.8(VCCB) U39.8(VCCB) ; also on sheet 7 8
RST_TGTMCU_B: C56.1 J20.2 J26.1 P1.43 R96.2 R197.1 SW3.3 SW3.4 ; also on sheet 6
SEL_ATX_AB: R196.1 U40.4(Y)
SEL_I2C: R181.1 U37.7(Y0) U40.2(A)
SEL_SPI: R180.1 U4.2(A) U37.6(Y1) U41.2(A)
SEL_UART: R195.1 U37.5(Y2)
SEL_USBP: U41.4(Y) ; also on sheet 3
SEL_USU: U4.4(Y) U10.9(S)
UART1_RX_TGTMCU: U12.2(1Y1) ; also on sheet 6
UART1_TX_TGTMCU: U12.4(2Y1) ; also on sheet 6
USB0_RDN: U10.2(1D-) ; also on sheet 3
USB0_RDP: U10.1(1D+) ; also on sheet 3
USB_EN: R85.2 R86.1 U4.1(B) U36.6(~{OE})
USB_VBUS_IN: R85.1 ; also on sheet 3
N27564961: J56.2(B1) U9.1(1Y0)
N27564977: U9.4(2Z) U36.3(2D+)
N27564985: R180.2 U9.2(1S) U9.10(2S)
N27565008: J56.8(B4) U9.13(4Y0)
N27565012: U9.12(4Z) U36.4(2D-)
N27566011: R196.2 U7.10(2S) U36.9(S)
N27566977: J68.7(A4) U7.12(4Z)
N27567064: J57.2(B1) U9.15(1Y1)
N27567073: J57.4(B2) U9.11(4Y1)
N27568724: U9.7(3Y1) U12.9(1Z)
N27568733: U9.3(2Y1) U12.6(2Z)
N27568769: J57.6(B3) U12.1(1Y0)
N27568772: J57.8(B4) U12.3(2Y0)
N27568943: R195.2 U12.7(2S) U12.8(1S)
N27589429: J54.4(B2) P1.39
N27589441: U7.16(1Z) U36.1(1D+)
N27589450: U7.4(2Z) U36.2(1D-)
N27590092: J58.1(A1) U13.2(A1)
N27590096: J58.2(B1) P1.16
N27590101: J58.3(A2) U13.3(A2)
N27590105: J58.4(B2) P1.13
N27590110: J58.5(A3) U13.4(A3)
N27590114: J58.6(B3) P1.14
N27590119: J58.7(A4) U13.5(A4)
N27590123: J58.8(B4) P1.15
N27590380: R18.2 R33.2 U6.12(OE)
N27590486: R46.2 R87.1 U13.12(OE)
N27591285: R38.2 R44.1 U8.12(OE)
N27591289: J56.1(A1) U8.2(A1)
N27591293: J56.3(A2) U8.3(A2)
N27591297: J56.5(A3) U8.4(A3)
N27591301: J56.7(A4) U8.5(A4)
N27592346: J56.4(B2) U9.5(2Y0)
N27592356: J56.6(B3) U9.9(3Y0)
N27592514: R43.2 R45.1 U11.12(OE)
N27592518: J57.1(A1) U11.2(A1)
N27592522: J57.3(A2) U11.3(A2)
N27618159: J54.3(A2) P1.40
N27622020: J45.1 R77.2 U24.5(A1)
N27625342: J22.3 R76.2 RT1.1
N27627038: J61.2 P1.21
N27627041: J24.2 P1.41 TP9.1(Pin1)
N27627050: J24.1 P1.42 TP10.1(Pin1)
N27627059: J62.2 P1.20
N27633845: J59.4(B2) P1.55 R251.2
N27634201: J59.2(B1) P1.56 R252.2
N27634211: J59.6(B3) P1.54 R250.2
N27643462: R90.2 R165.1 U24.6(OE)
N27777814: J20.1 R79.2 U24.4(A2)
N27957766: U37.3(Y3) U40.1(B)
N27958897: J62.1 SW6.2 U37.1(A) U39.2(1A)
N27966495: R42.2 R237.2 U5.12(OE)
N27966497: J55.1(A1) R179.2 R190.2 U5.2(A1)
N27966499: J55.3(A2) R174.2 R191.2 U5.3(A2)
N27966501: J55.5(A3) R173.2 R192.2 U5.4(A3)
N27966503: J55.7(A4) R172.2 R193.2 U5.5(A4)
N27968174: J54.8(B4) U7.1(1Y0)
N27968201: J55.2(B1) U7.15(1Y1)
N27968211: J55.4(B2) U7.3(2Y1)
N27968280: J68.5(A3) U7.8(3Z)
N27968923: J57.7(A4) U11.5(A4)
N27969320: J55.6(B3) U7.9(3Y0)
N27969333: J55.8(B4) U7.13(4Y0)
N27969338: U7.7(3Y1) U9.16(1Z)
N27969347: U7.11(4Y1) U9.8(3Z)
N27970206: R181.2 U7.2(1S)
N28021319: J61.1 SW5.2 U37.2(B) U39.3(2A)
N28107783: J54.7(A4) U7.5(2Y0)
N28108957: J57.5(A3) U11.4(A3)
N28112092: J45.2 P1.26
N28149982: C82.1 U22.3(XB) Y1.1(IN/OUT)
N28149990: C83.1 U22.2(XA) Y1.3(OUT/IN)
N28151082: C85.2 C86.1 J18.3
N28151436: C85.1 U22.10(CLK0)
N28152521: R239.2 U22.5(SDA)
N28152524: R240.2 U22.4(SCL)
N28775709: R244.2 U10.8(D+)
N28775712: R245.2 U10.7(D-)
N29343385: C55.1 J25.2 P1.27 Q2.3(C) R60.1 SW2.1 SW2.2
N29344136: Q1.1(BASE) R64.2 R93.1
N29345137: Q2.1(B) R16.2 R78.2
N29345138: Q1.3(COLLECTOR) R78.1
N29362741: R84.1 SW5.3
N29362872: R83.2 SW6.1
N29362980: R80.2 SW6.3
N29363265: R82.2 SW5.1
N29697733: J68.1(A1) U36.8(D+)
N29697736: J68.3(A2) U36.7(D-)
N29713504: R55.2 SW7.1
N29713520: SW7.2 U38.2(1A) U41.1(B)
N29713524: R57.1 SW7.3
N29774266: J59.1(A1) R256.2 U14.2(A1)
N29774271: J59.3(A2) R257.2 U14.3(A2)
N29774275: J59.5(A3) R258.2 U14.4(A3)
N29774848: R47.2 R88.1 U14.12(OE)

Not connected (* = marked no-connect by the designer): U14 5(A4)* 7(B4)*; U22 6(CLK2)* 9(CLK1)*; U38 3(2A)* 6(2B)*; Y1 4(NC)*

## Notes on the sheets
sheet 9
- i
- Note: J54
  1-3&2-4: PN76xx I2CM as leader - default
  3-5&4-6: PN76xx I2CM as follower - option
  5-7&6-8: PN76xx I2CA (ATX) as follower - default
- I2CM_SCL
- I2CM_SDA
- I2CM_SCL
- I2CM_SDA
- I2CA_SCL
- I2CA_SDA
- I2C_SDA
- GND
- I3C_SDA
- i
- Note:(NX3L2467)
  SEL: 0 (Y0 when I2C), 1 (Y1 when I3C)
- I2C_SCL
- I3C_SCL
- BIT0
- i
- Note:(NX3DV221)
  SEL: 0 (1D when I2C or I3C), 1 (2D when UART or SPI)
- BIT1
- I2C_SDA/I3C_SDA
- I2C_SCL/I3C_SCL
- HSUART_RX/SPIA_MISO
- HSUART_CTS/SPIA_SCK/I2C_SCL/I3C_SCL
- HSUART_RX/SPIA_MISO/I2C_SDA/I3C_SDA
- PNEV7642MA INTERFACE
- HSUART_CTS/SPIA_SCK
- ATX_A
- SPIA_NSS
- ATX_B
- HSUART_RTS/SPIA_NSS
- SPIA_MISO
- HSUART_RTS/SPIA_NSS/BIT0
- HSUART_TX/SPIA_MOSI/BIT1
- SPIA_MOSI
- i
- Layout Note:
  ==========
  Maintain 90 ohm differential impedance on USB0_ RDP/RDN and ATX_USB_DP/DN signals
- HSUART_TX/SPIA_MOSI
- SPIA_SCK
- ATX_C
- HSUART_RTS/SPIA_NSS/USB D+/BIT0
- i
- Note:(NX3DV3899)
  SEL: 0 (Y0 when SPI), 1 (Y1 when UART)
- HSUART_TX/SPIA_MOSI/USB D-/BIT1
- ATX_D
- i
- i
- Note:(NX3DV221)
  SEL:
  0 (1D when both USB_VBUS is 5V and SEL_SPI is HIGH),
  1 (2D when USB_VBUS is 0 or SEL_SPI is LOW)
- GND
- Note:USB_VBUS
  4.4V to 5.25V -> USB
  0 -> others
- i
- SPI has higher priority than USB when both are valid.
  Set SEL_SPI HIGH to use USB.
- HSUART_CTS
- HSUART_RTS
- HSUART_TX
- i
- Note:(NX3L2467)
  SEL: 0 (Y0 when ARDUINO UART), 1 (Y1 when OPENSDA UART)
- SPIM_MISO
- HSUART_RX
- SPIM_MOSI
- SPIM_SCLK
- SPIM_SSN
- GND
- CLK_AUX
- IO_AUX
- INT_AUX
sheet 10
- NFC CLOCK & RESET
- GND
- AD1
- i
- Note:+3850ppm/K (0C ~100C)
  0C: 100ohm : 0.63V
  100C: 491.363174125ohm : 1.78V
- CLK
- AUX1
- i
- Note: Si5351A
  Blank IC,
  No Boot-up frequency
  I2C Addr (Deafult): 60
- AUX2
- PNEV7642MA INTERFACE
- GND
- SEL_I2C (00)
- SEL_SPI (01)
- SEL_UART (10)
- PRD1
- i
- SEL_I3C (11)
- Note:SEL_ATX_AB
  0: I2C/I3C
  1: SPI/UART
- PRD2
- HOST_SEL0
- HOST_SEL1
- i
- HOSTSEL2
- HOSTSEL1
- HOSTSEL0
- I2C
- 0
- 0
- 0
- SPI
  (default)
- 0
- 0
- 1
- UART
- 0
- 1
- 0
- I3C
- 0
- 1
- 1
- USB
- 1
- 0
- 0
- SPI
- 1
- 0
- 1
- USB
- 1
- 1
- 0
- USB
- 1
- 1
- 1
- DWL_REQ
- IRQ
- VEN
